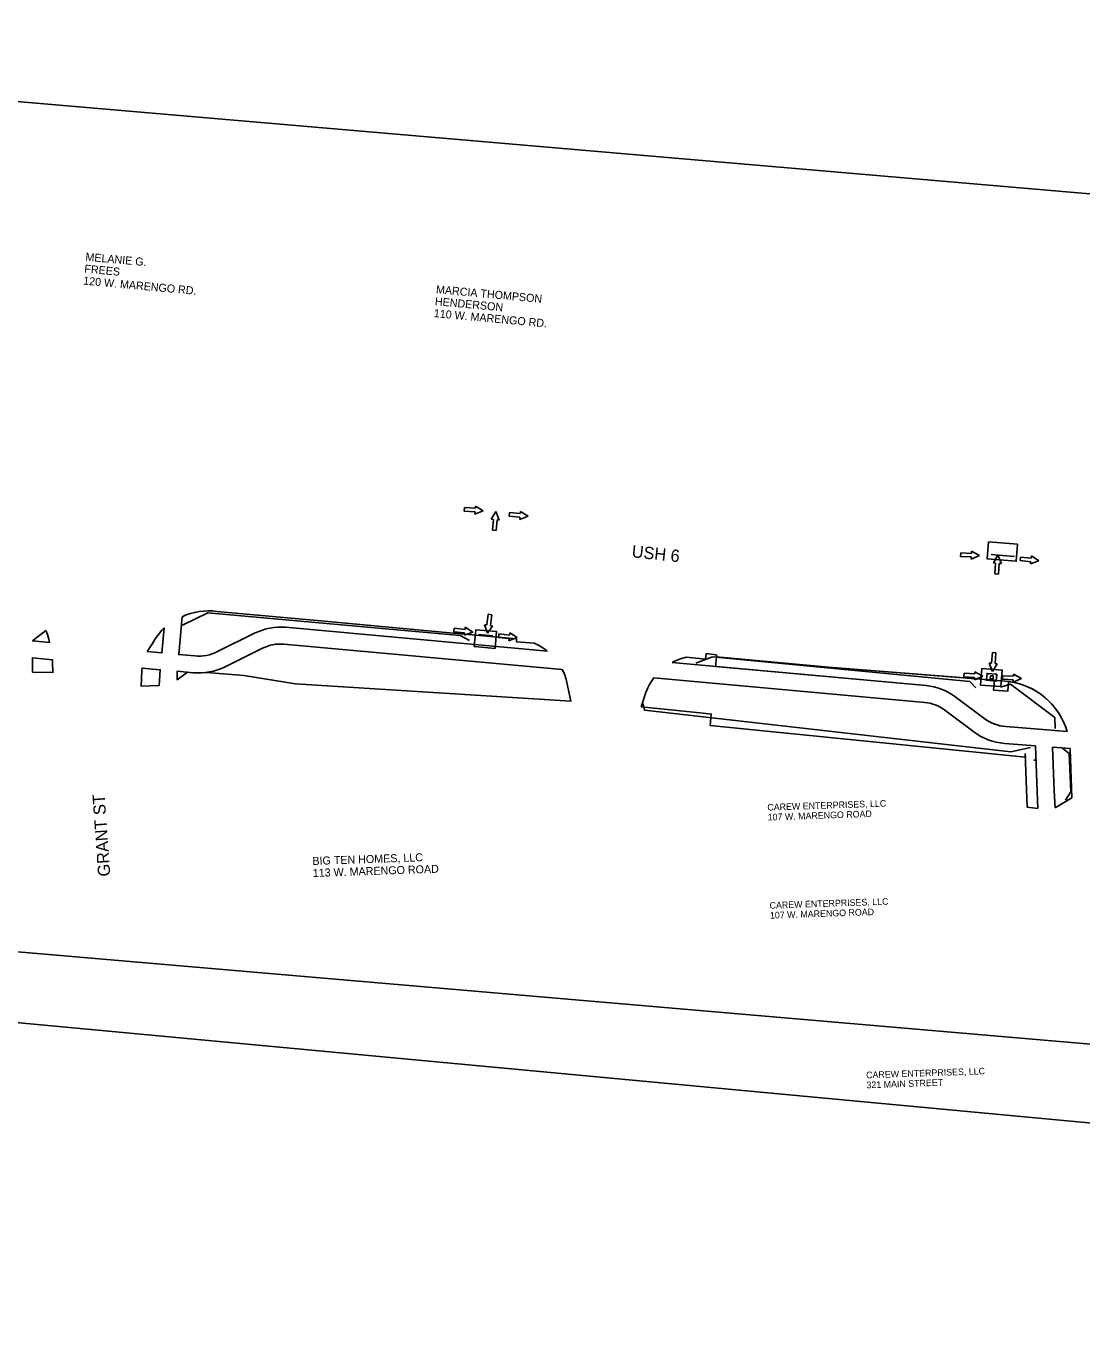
# Model space of a CAD drawing. Extents: x 20499351 to 20505779, y 7953198 to 7954637.
# Drawn here: x 20500564.2 to 20500937.9, y 7953706.6 to 7954173.4 of the extents above; entities that cross this region are included whole.
import ezdxf

# ---------------------------------------------------------------- set-up
doc = ezdxf.new("R2010")
doc.units = 0
for name, color, linetype in [('_CIVIL_CONSTRUCTION', 7, 'Continuous'), ('Contours Major', 7, 'Continuous'), ('Contours Minor', 7, 'Continuous'), ('NamedBoundary', 7, 'Continuous'), ('Terrain', 7, 'Continuous'), ('TL_GroundIntercept', 7, 'Continuous')]:
    doc.layers.add(name, color=color, linetype=linetype)

msp = doc.modelspace()

# ---------------------------------------------------------------- linework, layer by layer
at = {"layer": '_CIVIL_CONSTRUCTION'}
for p, q in [((20500719.27, 7954001.78), (20500719.37, 7954003.05)), ((20500723.07, 7954001.48), (20500719.27, 7954001.78)), ((20500719.37, 7954003.05), (20500723.17, 7954002.75)), ((20500725.98, 7954001.89), (20500723.01, 7954000.69)), ((20500723.17, 7954002.75), (20500723.24, 7954003.54)), ((20500723.24, 7954003.54), (20500725.98, 7954001.89)), ((20500723.01, 7954000.69), (20500723.07, 7954001.48)), ((20500728.79, 7953998.87), (20500730.43, 7954001.61)), ((20500728.79, 7953998.87), (20500730.43, 7954001.61)), ((20500729.58, 7953998.81), (20500728.79, 7953998.87)), ((20500729.58, 7953998.81), (20500728.79, 7953998.87)), ((20500729.29, 7953995), (20500729.58, 7953998.81)), ((20500729.29, 7953995), (20500729.58, 7953998.81)), ((20500730.43, 7954001.61), (20500731.64, 7953998.65)), ((20500730.43, 7954001.61), (20500731.64, 7953998.65)), ((20500730.85, 7953998.71), (20500730.56, 7953994.9)), ((20500730.85, 7953998.71), (20500730.56, 7953994.9)), ((20500731.64, 7953998.65), (20500730.85, 7953998.71)), ((20500731.64, 7953998.65), (20500730.85, 7953998.71)), ((20500735.14, 7953999.97), (20500735.26, 7954001.24)), ((20500738.94, 7953999.61), (20500735.14, 7953999.97)), ((20500735.26, 7954001.24), (20500739.06, 7954000.88)), ((20500741.85, 7953999.98), (20500738.87, 7953998.82)), ((20500738.87, 7953998.82), (20500738.94, 7953999.61)), ((20500739.06, 7954000.88), (20500739.14, 7954001.67)), ((20500739.14, 7954001.67), (20500741.85, 7953999.98)), ((20500730.56, 7953994.9), (20500729.29, 7953995)), ((20500730.56, 7953994.9), (20500729.29, 7953995)), ((20500895, 7953985.73), (20500895.06, 7953987)), ((20500898.81, 7953985.54), (20500895, 7953985.73)), ((20500895.06, 7953987), (20500898.87, 7953986.81)), ((20500901.7, 7953986.03), (20500898.77, 7953984.75)), ((20500898.77, 7953984.75), (20500898.81, 7953985.54)), ((20500898.87, 7953986.81), (20500898.91, 7953987.6)), ((20500898.91, 7953987.6), (20500901.7, 7953986.03)), ((20500906.63, 7953983.4), (20500908.28, 7953986.15)), ((20500907.43, 7953983.34), (20500906.63, 7953983.4)), ((20500907.14, 7953979.54), (20500907.43, 7953983.34)), ((20500908.28, 7953986.15), (20500909.49, 7953983.19)), ((20500908.69, 7953983.25), (20500908.41, 7953979.44)), ((20500909.49, 7953983.19), (20500908.69, 7953983.25)), ((20500916.08, 7953984.23), (20500916.21, 7953985.49)), ((20500919.88, 7953983.85), (20500916.08, 7953984.23)), ((20500916.21, 7953985.49), (20500920.01, 7953985.11)), ((20500922.79, 7953984.19), (20500919.8, 7953983.06)), ((20500919.8, 7953983.06), (20500919.88, 7953983.85)), ((20500920.01, 7953985.11), (20500920.09, 7953985.9)), ((20500920.09, 7953985.9), (20500922.79, 7953984.19)), ((20500908.41, 7953979.44), (20500907.14, 7953979.54)), ((20500727.23, 7953961.43), (20500727.7, 7953965.22)), ((20500727.7, 7953965.22), (20500728.96, 7953965.06)), ((20500728.96, 7953965.06), (20500728.49, 7953961.27)), ((20500715.59, 7953959), (20500715.72, 7953960.26)), ((20500715.72, 7953960.26), (20500719.52, 7953959.88)), ((20500719.52, 7953959.88), (20500719.6, 7953960.67)), ((20500719.6, 7953960.67), (20500722.3, 7953958.95)), ((20500727.51, 7953958.51), (20500726.44, 7953961.53)), ((20500726.44, 7953961.53), (20500727.23, 7953961.43)), ((20500729.28, 7953961.18), (20500727.51, 7953958.51)), ((20500728.49, 7953961.27), (20500729.28, 7953961.18)), ((20500719.39, 7953958.61), (20500715.59, 7953959)), ((20500722.3, 7953958.95), (20500719.31, 7953957.82)), ((20500719.31, 7953957.82), (20500719.39, 7953958.61)), ((20500731.33, 7953956.98), (20500731.46, 7953958.25)), ((20500735.13, 7953956.62), (20500731.33, 7953956.98)), ((20500731.46, 7953958.25), (20500735.25, 7953957.88)), ((20500738.04, 7953956.97), (20500735.06, 7953955.82)), ((20500735.06, 7953955.82), (20500735.13, 7953956.62)), ((20500735.25, 7953957.88), (20500735.33, 7953958.67)), ((20500735.33, 7953958.67), (20500738.04, 7953956.97)), ((20500905.98, 7953947.87), (20500906.28, 7953951.67)), ((20500906.28, 7953951.67), (20500907.55, 7953951.57)), ((20500907.55, 7953951.57), (20500907.25, 7953947.77)), ((20500906.39, 7953944.97), (20500905.19, 7953947.93)), ((20500905.19, 7953947.93), (20500905.98, 7953947.87)), ((20500908.04, 7953947.71), (20500906.39, 7953944.97)), ((20500907.25, 7953947.77), (20500908.04, 7953947.71)), ((20500896.18, 7953943.08), (20500896.26, 7953944.35)), ((20500899.99, 7953942.83), (20500896.18, 7953943.08)), ((20500896.26, 7953944.35), (20500900.07, 7953944.1)), ((20500902.89, 7953943.28), (20500899.94, 7953942.04)), ((20500899.94, 7953942.04), (20500899.99, 7953942.83)), ((20500900.07, 7953944.1), (20500900.12, 7953944.89)), ((20500900.12, 7953944.89), (20500902.89, 7953943.28)), ((20500909.89, 7953942.21), (20500909.97, 7953943.48)), ((20500913.7, 7953942), (20500909.89, 7953942.21)), ((20500909.97, 7953943.48), (20500913.78, 7953943.27)), ((20500916.6, 7953942.47), (20500913.66, 7953941.2)), ((20500913.66, 7953941.2), (20500913.7, 7953942)), ((20500913.78, 7953943.27), (20500913.82, 7953944.06)), ((20500913.82, 7953944.06), (20500916.6, 7953942.47))]:
    msp.add_line(p, q, dxfattribs=at)
at = {"layer": 'Contours Major'}
for p, q in [((20500655.89, 7953960.61), (20500748.67, 7953952.18)), ((20500631.89, 7953952), (20500645.17, 7953958.6)), ((20500647.84, 7953953.23), (20500634.56, 7953946.62)), ((20500753.95, 7953945.67), (20500655.34, 7953954.63)), ((20500808.63, 7953950.91), (20500804.87, 7953951.34)), ((20500808.56, 7953950.16), (20500808.63, 7953950.91)), ((20500792.88, 7953948.16), (20500882.85, 7953939.98)), ((20500628.13, 7953944.6), (20500641.23, 7953943.52)), ((20500786.43, 7953942.72), (20500882.31, 7953934.01)), ((20500781.85, 7953932.48), (20500783.27, 7953936.77)), ((20500893.03, 7953936.07), (20500903.27, 7953928.41)), ((20500889.43, 7953931.27), (20500899.68, 7953923.6)), ((20500911.07, 7953925.46), (20500932.78, 7953923.74)), ((20500910.6, 7953919.48), (20500921.59, 7953918.61)), ((20500921.59, 7953918.61), (20500922.19, 7953902.42)), ((20500927.61, 7953918.14), (20500928.19, 7953902.64)), ((20500933.79, 7953917.64), (20500927.61, 7953918.13)), ((20500934.39, 7953900.27), (20500933.79, 7953917.5)), ((20500922.19, 7953902.42), (20500922.42, 7953896.4)), ((20500928.19, 7953902.64), (20500928.56, 7953896.65)), ((20500928.56, 7953896.65), (20500934.39, 7953900.27))]:
    msp.add_line(p, q, dxfattribs=at)
for points in [[(20500744.1, 7953954.94), (20500737.71, 7953955.48), (20500737.73, 7953956.53), (20500711.5, 7953958.93), (20500667.11, 7953963.07), (20500631.62, 7953966.26)], [(20500606.9, 7953952.05), (20500608.78, 7953954.92), (20500609.82, 7953956.53), (20500610.91, 7953958.09), (20500612.12, 7953959.57), (20500612.96, 7953960.41), (20500612.14, 7953951.57), (20500606.9, 7953952.05)], [(20500619.35, 7953964.38), (20500618.11, 7953950.96), (20500623.84, 7953950.49)], [(20500571.11, 7953959.52), (20500566.37, 7953955.78), (20500572.32, 7953955.23), (20500572.12, 7953956.45), (20500571.7, 7953958.1), (20500571.11, 7953959.52)], [(20500804.87, 7953951.34), (20500804.7, 7953949.35), (20500797.78, 7953949.99)], [(20500566.34, 7953944.76), (20500573.54, 7953944.59), (20500573.37, 7953948.25), (20500573.36, 7953949.11), (20500566.31, 7953949.76), (20500566.34, 7953944.76)], [(20500910.79, 7953941.56), (20500848.24, 7953946.53), (20500808.56, 7953950.16)], [(20500623.29, 7953944.52), (20500617.57, 7953945.04), (20500617.56, 7953942.05), (20500621.17, 7953944.71), (20500623.29, 7953944.52), (20500628.13, 7953944.6)], [(20500641.23, 7953943.52), (20500659.48, 7953940.57), (20500757.04, 7953934.51), (20500755.63, 7953941.01)], [(20500922.42, 7953896.4), (20500918.59, 7953896.93), (20500917.92, 7953915.82), (20500917.97, 7953914.65), (20500806.34, 7953925.87), (20500806.7, 7953929.88), (20500803.83, 7953930.2), (20500781.85, 7953932.48)]]:
    msp.add_lwpolyline(points, dxfattribs=at)
msp.add_lwpolyline([(20500611.23, 7953940.06), (20500604.78, 7953939.77), (20500605, 7953945.31), (20500605.13, 7953946.19), (20500611.59, 7953945.59)], close=True, dxfattribs=at)
for centre, radius, start, end in [((20500628.84, 7953943.43), 23, 83.0584, 114.3804), ((20500654.08, 7953940.69), 20, 84.8067, 116.4333), ((20500625.21, 7953965.43), 15, 264.6514, 296.4312), ((20500654.08, 7953940.69), 14, 84.8067, 116.4333), ((20500736.12, 7953936.6), 20, 51.1592, 66.4896), ((20500625.21, 7953965.43), 21, 264.7546, 296.4333), ((20500802.26, 7953930.49), 20, 102.9322, 117.9663), ((20500736.12, 7953936.6), 20, 12.7378, 26.9786), ((20500736.12, 7953936.6), 20, 12.6715, 26.9786), ((20500802.26, 7953930.49), 20, 142.3169, 161.7253), ((20500908.81, 7953916.63), 25, 16.5027, 85.4564), ((20500881.04, 7953920.06), 20, 53.1801, 84.8067), ((20500881.04, 7953920.06), 14, 53.1801, 84.8067), ((20500912.26, 7953940.41), 15, 233.1801, 265.4563), ((20500912.26, 7953940.41), 21, 233.1801, 265.4563), ((20500908.81, 7953916.63), 25, 1.9853, 2.2978)]:
    msp.add_arc(centre, radius, start, end, dxfattribs=at)
at = {"layer": 'Contours Minor'}
for p, q in [((20500914.18, 7953985.72), (20500905.86, 7953986.34)), ((20500724.34, 7953958.05), (20500729.32, 7953957.61)), ((20500808.25, 7953946.76), (20500882.85, 7953939.98)), ((20500904.41, 7953943.93), (20500904.58, 7953943.91)), ((20500904.58, 7953943.91), (20500904.76, 7953944.07)), ((20500904.78, 7953944.24), (20500904.76, 7953944.07)), ((20500907.31, 7953941.6), (20500907.33, 7953941.76)), ((20500907.51, 7953941.92), (20500907.33, 7953941.76)), ((20500907.68, 7953941.9), (20500907.51, 7953941.92)), ((20500911.99, 7953941.43), (20500912, 7953941.46)), ((20500893.03, 7953936.07), (20500903.31, 7953928.38)), ((20500911.13, 7953925.43), (20500932.78, 7953923.74)), ((20500921.58, 7953913.59), (20500920.92, 7953913.56))]:
    msp.add_line(p, q, dxfattribs=at)
for points in [[(20500904.94, 7953990.85), (20500904.46, 7953984.83), (20500914.72, 7953984.01), (20500915.2, 7953990.03)], [(20500723.33, 7953959.74), (20500730.68, 7953959.09), (20500730.14, 7953953.11), (20500722.79, 7953953.77)], [(20500902.56, 7953946.05), (20500909.79, 7953945.48), (20500909.32, 7953939.59), (20500902.09, 7953940.16)], [(20500904.24, 7953941.84), (20500907.65, 7953941.57), (20500907.85, 7953943.99), (20500904.44, 7953944.26)], [(20500904.44, 7953944.26), (20500907.85, 7953943.99), (20500907.65, 7953941.57), (20500904.24, 7953941.84)], [(20500904.41, 7953941.83), (20500904.24, 7953941.84), (20500904.27, 7953942.18), (20500904.44, 7953942.16)], [(20500904.58, 7953943.91), (20500904.41, 7953943.93), (20500904.44, 7953944.26), (20500904.61, 7953944.25)], [(20500905.58, 7953943.46), (20500906.59, 7953943.38), (20500906.51, 7953942.37), (20500905.5, 7953942.45)], [(20500907.65, 7953941.57), (20500907.48, 7953941.58), (20500907.51, 7953941.92), (20500907.68, 7953941.9)], [(20500907.82, 7953943.65), (20500907.65, 7953943.67), (20500907.68, 7953944), (20500907.85, 7953943.99)]]:
    msp.add_lwpolyline(points, close=True, dxfattribs=at)
for points in [[(20500619.47, 7953961.33), (20500628.39, 7953965.68), (20500717.8, 7953957.71), (20500721.06, 7953955.95)], [(20500900.42, 7953939.17), (20500898.36, 7953941.38), (20500807.13, 7953950.2), (20500801.24, 7953947.96)], [(20500808.56, 7953950.16), (20500808.45, 7953948.97), (20500808.42, 7953948.59)], [(20500907.01, 7953941.86), (20500848.24, 7953946.53), (20500808.56, 7953950.16)], [(20500912, 7953941.46), (20500911.72, 7953937.97), (20500906.74, 7953938.37), (20500907.01, 7953941.86)], [(20500909.17, 7953939.4), (20500912.74, 7953940.46), (20500928.42, 7953928.66), (20500928.57, 7953924.78)], [(20500782.62, 7953933.53), (20500783.08, 7953931.32), (20500912.82, 7953916.48), (20500919.82, 7953918)], [(20500930.78, 7953918.01), (20500933.52, 7953915.95), (20500934.05, 7953902.33), (20500932.22, 7953899.44)]]:
    msp.add_lwpolyline(points, dxfattribs=at)
for centre, radius, start, end in [((20500908.78, 7953916.6), 25.04, 16.5619, 82.622), ((20500881.04, 7953920.06), 20, 53.1801, 84.8067), ((20500912.3, 7953940.39), 15, 233.1801, 265.5205)]:
    msp.add_arc(centre, radius, start, end, dxfattribs=at)
msp.add_open_spline([(20500808.42, 7953948.59), (20500808.38, 7953948.23), (20500808.34, 7953947.71), (20500808.3, 7953947.33), (20500808.25, 7953946.76)], degree=3, dxfattribs=at)
at = {"layer": 'NamedBoundary'}
msp.add_lwpolyline([(20500359.01, 7954164.14), (20500333.3, 7953865.25), (20501270.32, 7953784.65), (20501296.03, 7954083.54)], close=True, dxfattribs=at)
at = {"layer": 'Terrain'}
msp.add_lwpolyline([(20501791.06, 7953833.84), (20501779.66, 7953706.56), (20499351.13, 7953933.78), (20499411.85, 7954636.65), (20501855.07, 7954405.25), (20501814.1, 7954091.19), (20501791.1, 7953834.34)], dxfattribs=at)

# ---------------------------------------------------------------- texts
at = {"layer": 'TL_GroundIntercept'}
for s, height, rotation, p in [('MELANIE G.', 2.835, 354.7645, (20500584.99, 7954090.49)), ('FREES', 2.835, 354.7645, (20500584.6, 7954086.26)), ('120 W. MARENGO RD.', 2.8346, 354.7645, (20500584.21, 7954082.03)), ('MARCIA THOMPSON', 2.8346, 354.7645, (20500709.15, 7954078.96)), ('HENDERSON', 2.835, 354.7645, (20500708.76, 7954074.72)), ('110 W. MARENGO RD.', 2.8346, 354.7645, (20500708.37, 7954070.49)), ('USH 6', 4.32, 354.0545, (20500778.41, 7953985.43)), ('GRANT ST', 4.32, 94.0951, (20500593.93, 7953872.52)), ('CAREW ENTERPRISES, LLC', 2.3424, 1.9645, (20500826.63, 7953895.69)), ('107 W. MARENGO ROAD', 2.3424, 1.9645, (20500826.75, 7953892.18)), ('BIG TEN HOMES, LLC', 2.8346, 1.9645, (20500665.51, 7953876.43)), ('113 W. MARENGO ROAD', 2.8346, 1.9645, (20500665.65, 7953872.18)), ('CAREW ENTERPRISES, LLC', 2.3424, 1.9645, (20500827.42, 7953860.94)), ('107 W. MARENGO ROAD', 2.3424, 1.9645, (20500827.54, 7953857.43)), ('CAREW ENTERPRISES, LLC', 2.3424, 1.9645, (20500861.61, 7953800.86)), ('321 MAIN STREET', 2.3424, 1.9645, (20500861.73, 7953797.34))]:
    msp.add_text(s, height=height, rotation=rotation, dxfattribs=at).set_placement(p)

doc.saveas('drawing.dxf')
